Omron CX-Programmer project NuevoProyecto (CX-Programmer 9.50)

# PLC NewPLC1: CP1L-E EM

## Program P12_2 (cyclic task 0)
Local symbols
Etapa_0 10.00 BOOL
Etapa_1 10.01 BOOL
Etapa_2 10.02 BOOL
Etapa_3 10.03 BOOL
Etapa_4 10.04 BOOL
Etapa_5 10.05 BOOL
Etapa_6 10.06 BOOL
Etapa_7 10.07 BOOL
Etapa_8 10.08 BOOL
F1 0.01 BOOL
F2 0.02 BOOL
F3 0.03 BOOL
F4 0.04 BOOL
P 0.00 BOOL
Pm 15.00 BOOL
Rd1 100.00 BOOL
Rd2 100.02 BOOL
Ri1 100.01 BOOL
Ri2 100.03 BOOL

### Section Sección1_Programa_principal
; Etapas 0 ... 8

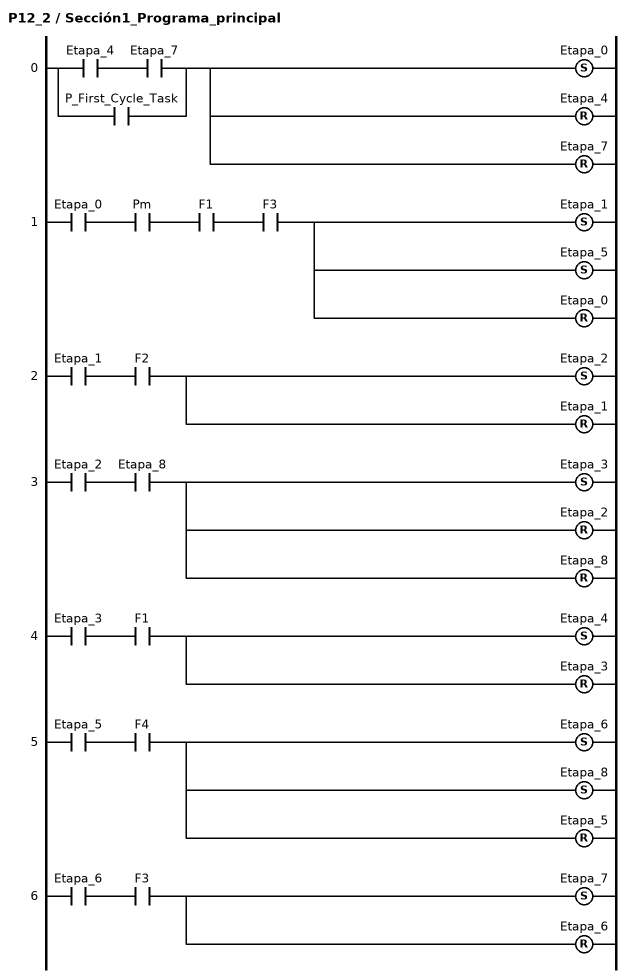
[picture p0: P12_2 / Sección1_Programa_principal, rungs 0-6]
; rung 0
LD Etapa_4
AND Etapa_7
OR P_First_Cycle_Task
SET Etapa_0
RSET Etapa_4
RSET Etapa_7
; rung 1
LD Etapa_0
AND Pm
AND F1
AND F3
SET Etapa_1
SET Etapa_5
RSET Etapa_0
; rung 2
LD Etapa_1
AND F2
SET Etapa_2
RSET Etapa_1
; rung 3
LD Etapa_2
AND Etapa_8
SET Etapa_3
RSET Etapa_2
RSET Etapa_8
; rung 4
LD Etapa_3
AND F1
SET Etapa_4
RSET Etapa_3
; rung 5
LD Etapa_5
AND F4
SET Etapa_6
SET Etapa_8
RSET Etapa_5
; rung 6
LD Etapa_6
AND F3
SET Etapa_7
RSET Etapa_6

### Section Sección2_Paro_memorizado

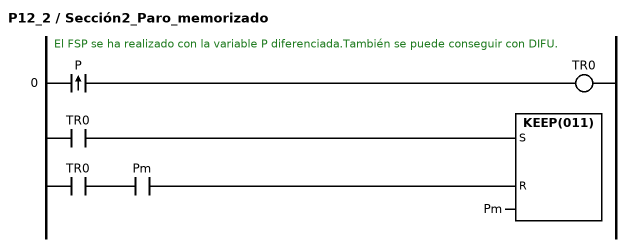
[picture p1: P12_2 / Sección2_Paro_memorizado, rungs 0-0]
; rung 0: El FSP se ha realizado con la variable P diferenciada.También se puede conseguir con DIFU.
@LD P
OUT TR0
LD TR0
AND Pm
KEEP(011) Pm

### Section Sección3_Salidas
; Salidas

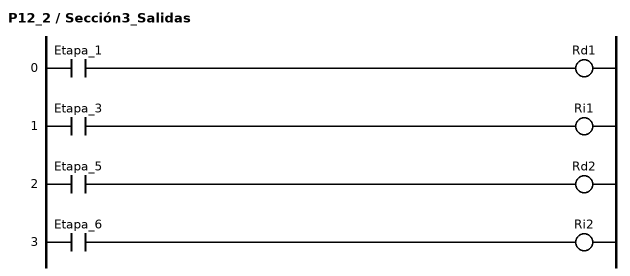
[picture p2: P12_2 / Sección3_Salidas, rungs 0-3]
; rung 0
LD Etapa_1
OUT Rd1
; rung 1
LD Etapa_3
OUT Ri1
; rung 2
LD Etapa_5
OUT Rd2
; rung 3
LD Etapa_6
OUT Ri2

### Section Sección4_END
; rung 0
END(001)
